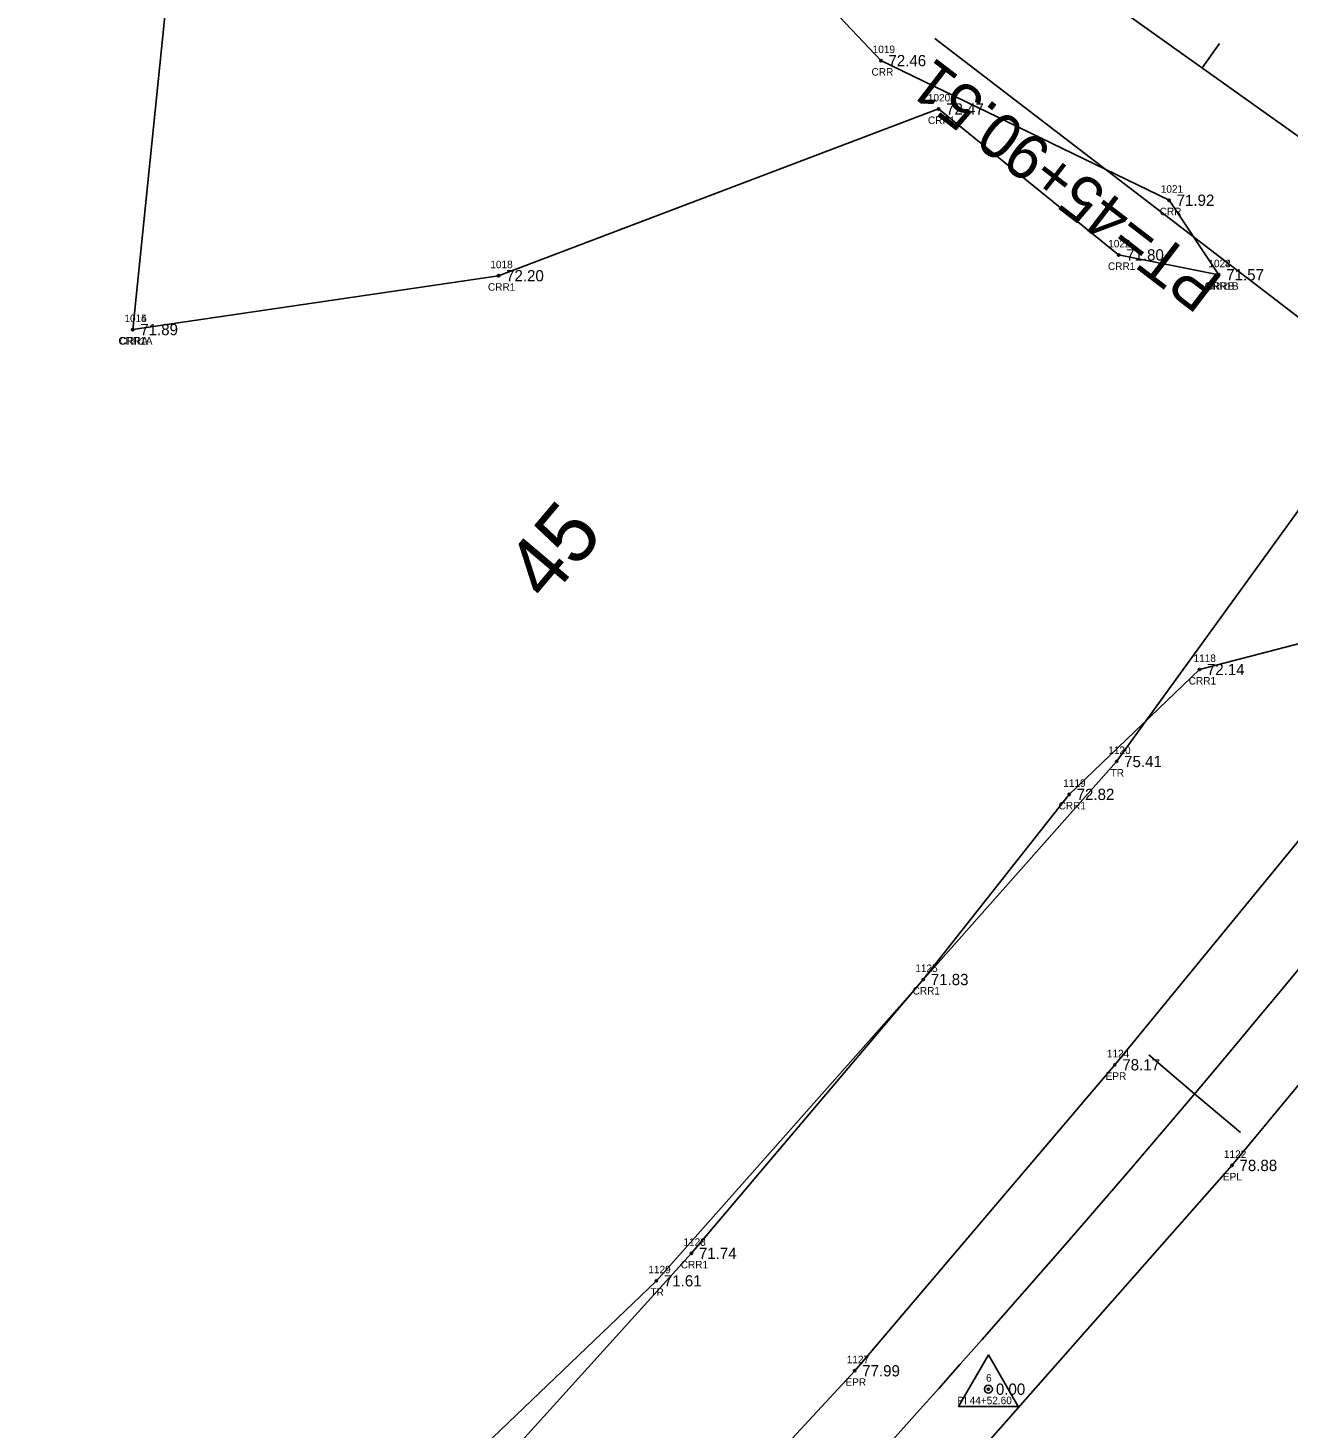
# Model space of a CAD drawing. Extents: x 2505249 to 2506333, y 912937 to 914171.
# Drawn here: x 2505580.7 to 2505748.6, y 913379.5 to 913565.9 of the extents above; entities that cross this region are included whole.
import ezdxf

# ---------------------------------------------------------------- set-up
doc = ezdxf.new("R2010")
doc.units = 0
for name, color, linetype in [('RD_EX_H2O', 7, 'Continuous'), ('RD_EX_H2O_txCode', 7, 'Continuous'), ('RD_EX_Road', 7, 'Continuous'), ('RD_EX_Road_txCode', 7, 'Continuous'), ('RD_EX_TX_H2O_ELEV', 7, 'Continuous'), ('RD_EX_TX_Road_ELEV', 7, 'Continuous'), ('RD_EX_TX_VEG_ELEV', 7, 'Continuous'), ('RD_EX_VEG', 7, 'Continuous'), ('RD_EX_VEG_txCode', 7, 'Continuous'), ('RD_HC_Cl', 7, 'Continuous'), ('RD_HC_Data', 7, 'Continuous'), ('RD_HC_Data_Tic', 7, 'Continuous'), ('RD_HC_Survey_ELEV', 7, 'Continuous'), ('RD_HC_TX_Sta50', 7, 'Continuous'), ('RD_HC_txCode', 7, 'Continuous'), ('RD_SMD_Locator', 7, 'Continuous')]:
    doc.layers.add(name, color=color, linetype=linetype)

msp = doc.modelspace()

# ---------------------------------------------------------------- linework, layer by layer
at = {"layer": 'RD_EX_H2O'}
for points in [[(2505594.65, 913525.76), (2505599.08, 913569.22), (2505647.5, 913611.03), (2505694.26, 913561.57), (2505732.63, 913542.98), (2505739.24, 913533.06)], [(2505594.65, 913525.76), (2505643.36, 913532.93), (2505701.94, 913555.13), (2505725.91, 913535.7), (2505739.24, 913533.06)], [(2505789.47, 913464.31), (2505758.18, 913486.1), (2505736.66, 913480.49), (2505719.32, 913463.86), (2505699.9, 913439.21), (2505669.03, 913402.75), (2505628.5, 913357.9), (2505593, 913316.39), (2505556.58, 913279.8), (2505487.72, 913211.38), (2505413.81, 913149.81), (2505341.31, 913072.1)]]:
    msp.add_lwpolyline(points, dxfattribs=at)
at = {"layer": 'RD_EX_Road'}
for points in [[(2505758.23, 913470.96), (2505754.11, 913462.85), (2505725.4, 913427.85), (2505690.77, 913387.11), (2505650.25, 913343.36), (2505607.72, 913300.12), (2505570.97, 913264.99), (2505501.53, 913196.72), (2505431.76, 913128.83), (2505356.25, 913055.37)], [(2505777.56, 913455.88), (2505770.31, 913449.85), (2505741, 913414.45), (2505705.55, 913374.27), (2505664.83, 913329.82), (2505624.02, 913288.23), (2505585.62, 913250.63), (2505516.95, 913183.5), (2505444.27, 913113.56), (2505370.6, 913041.78)]]:
    msp.add_lwpolyline(points, dxfattribs=at)
at = {"layer": 'RD_EX_VEG'}
msp.add_lwpolyline([(2506002.64, 913815.25), (2505883.7, 913669.64), (2505827.83, 913593.29), (2505814.43, 913589.15), (2505792.49, 913560.55), (2505725.64, 913468.24), (2505664.37, 913399.09), (2505478.33, 913221), (2505411.99, 913152.19), (2505339.13, 913074.53)], dxfattribs=at)
at = {"layer": 'RD_HC_Cl'}
msp.add_line((2505655.63, 913618.69), (2505757.7, 913545.85), dxfattribs=at)
msp.add_arc((2504276.95, 914656.3), 1909.83, 314.24205, 322.53164, dxfattribs=at)
at = {"layer": 'RD_HC_Data'}
for p, q in [((2505792.76, 913494.51), (2505701.43, 913564.51)), ((2505704.6, 913382.37), (2505708.57, 913389.25)), ((2505708.57, 913389.25), (2505712.54, 913382.37)), ((2505704.6, 913382.37), (2505712.54, 913382.37))]:
    msp.add_line(p, q, dxfattribs=at)
msp.add_circle((2505708.57, 913384.66), 0.529, dxfattribs=at)
at = {"layer": 'RD_HC_Data_Tic'}
for p, q in [((2505737.03, 913560.6), (2505739.35, 913563.86)), ((2505736.02, 913424), (2505729.91, 913429.16)), ((2505736.02, 913424), (2505742.13, 913418.84))]:
    msp.add_line(p, q, dxfattribs=at)
at = {"layer": 'RD_SMD_Locator'}
for centre in [(2505694.26, 913561.57), (2505701.94, 913555.13), (2505732.63, 913542.98), (2505725.91, 913535.7), (2505643.36, 913532.93), (2505739.24, 913533.06), (2505739.24, 913533.06), (2505594.65, 913525.76), (2505594.65, 913525.76), (2505736.66, 913480.49), (2505725.64, 913468.24), (2505719.32, 913463.86), (2505699.9, 913439.21), (2505725.4, 913427.85), (2505741, 913414.45), (2505669.03, 913402.75), (2505664.37, 913399.09), (2505690.77, 913387.11), (2505708.57, 913384.66)]:
    msp.add_circle(centre, 0.15, dxfattribs=at)

# ---------------------------------------------------------------- texts
at = {"layer": 'RD_EX_H2O_txCode'}
for s, p in [('1019', (2505693.16, 913562.57)), ('CRR', (2505693.01, 913559.57)), ('1020', (2505700.51, 913556.13)), ('CRR1', (2505700.52, 913553.13)), ('1021', (2505731.52, 913543.98)), ('CRR', (2505731.37, 913540.98)), ('1022', (2505724.52, 913536.7)), ('1018', (2505642.26, 913533.93)), ('CRR1', (2505724.49, 913533.7)), ('1023', (2505737.86, 913534.06)), ('1024', (2505737.86, 913534.06)), ('CRR1', (2505641.94, 913530.93)), ('CRR1B', (2505737.35, 913531.06)), ('CRRB', (2505737.52, 913531.06)), ('1014', (2505593.54, 913526.76)), ('1015', (2505593.54, 913526.76)), ('CRR1A', (2505592.74, 913523.76)), ('CRRA', (2505592.9, 913523.76)), ('1118', (2505735.88, 913481.49)), ('CRR1', (2505735.24, 913478.49)), ('1119', (2505718.54, 913464.86)), ('CRR1', (2505717.91, 913461.86)), ('1125', (2505698.84, 913440.21)), ('CRR1', (2505698.48, 913437.21)), ('1128', (2505667.97, 913403.75)), ('CRR1', (2505667.61, 913400.75))]:
    msp.add_text(s, height=1, dxfattribs=at).set_placement(p)
at = {"layer": 'RD_EX_Road_txCode'}
for s, p in [('1124', (2505724.34, 913428.85)), ('EPR', (2505724.18, 913425.85)), ('1122', (2505739.93, 913415.45)), ('EPL', (2505739.79, 913412.45)), ('1127', (2505689.71, 913388.11)), ('EPR', (2505689.54, 913385.11))]:
    msp.add_text(s, height=1, dxfattribs=at).set_placement(p)
at = {"layer": 'RD_EX_TX_H2O_ELEV'}
for s, p in [('72.46', (2505695.26, 913560.82)), ('72.47', (2505702.94, 913554.38)), ('71.92', (2505733.63, 913542.23)), ('71.80', (2505726.91, 913534.95)), ('72.20', (2505644.36, 913532.18)), ('71.57', (2505740.24, 913532.31)), ('71.57', (2505740.24, 913532.31)), ('71.89', (2505595.65, 913525.01)), ('71.89', (2505595.65, 913525.01)), ('72.14', (2505737.66, 913479.74)), ('72.82', (2505720.32, 913463.11)), ('71.83', (2505700.9, 913438.46)), ('71.74', (2505670.03, 913402))]:
    msp.add_text(s, height=1.5, dxfattribs=at).set_placement(p)
at = {"layer": 'RD_EX_TX_Road_ELEV'}
for s, p in [('78.17', (2505726.4, 913427.1)), ('78.88', (2505742, 913413.7)), ('77.99', (2505691.77, 913386.36))]:
    msp.add_text(s, height=1.5, dxfattribs=at).set_placement(p)
at = {"layer": 'RD_EX_TX_VEG_ELEV'}
for s, p in [('75.41', (2505726.64, 913467.49)), ('71.61', (2505665.37, 913398.34))]:
    msp.add_text(s, height=1.5, dxfattribs=at).set_placement(p)
at = {"layer": 'RD_EX_VEG_txCode'}
for s, p in [('1120', (2505724.53, 913469.24)), ('TR', (2505724.84, 913466.24)), ('1129', (2505663.3, 913400.09)), ('TR', (2505663.57, 913397.09))]:
    msp.add_text(s, height=1, dxfattribs=at).set_placement(p)
at = {"layer": 'RD_HC_Data'}
msp.add_text('PT=45+90.51', height=6, rotation=142.5316, dxfattribs=at).set_placement((2505739.96, 913532.46))
at = {"layer": 'RD_HC_Survey_ELEV'}
msp.add_text('0.00', height=1.5, dxfattribs=at).set_placement((2505709.57, 913383.91))
at = {"layer": 'RD_HC_TX_Sta50'}
msp.add_text('45', height=8, rotation=49.8162, dxfattribs=at).set_placement((2505649.79, 913489.29))
at = {"layer": 'RD_HC_txCode'}
for s, p in [('6', (2505708.26, 913385.66)), ('PI 44+52.60', (2505704.44, 913382.66))]:
    msp.add_text(s, height=1, dxfattribs=at).set_placement(p)

doc.saveas('drawing.dxf')
